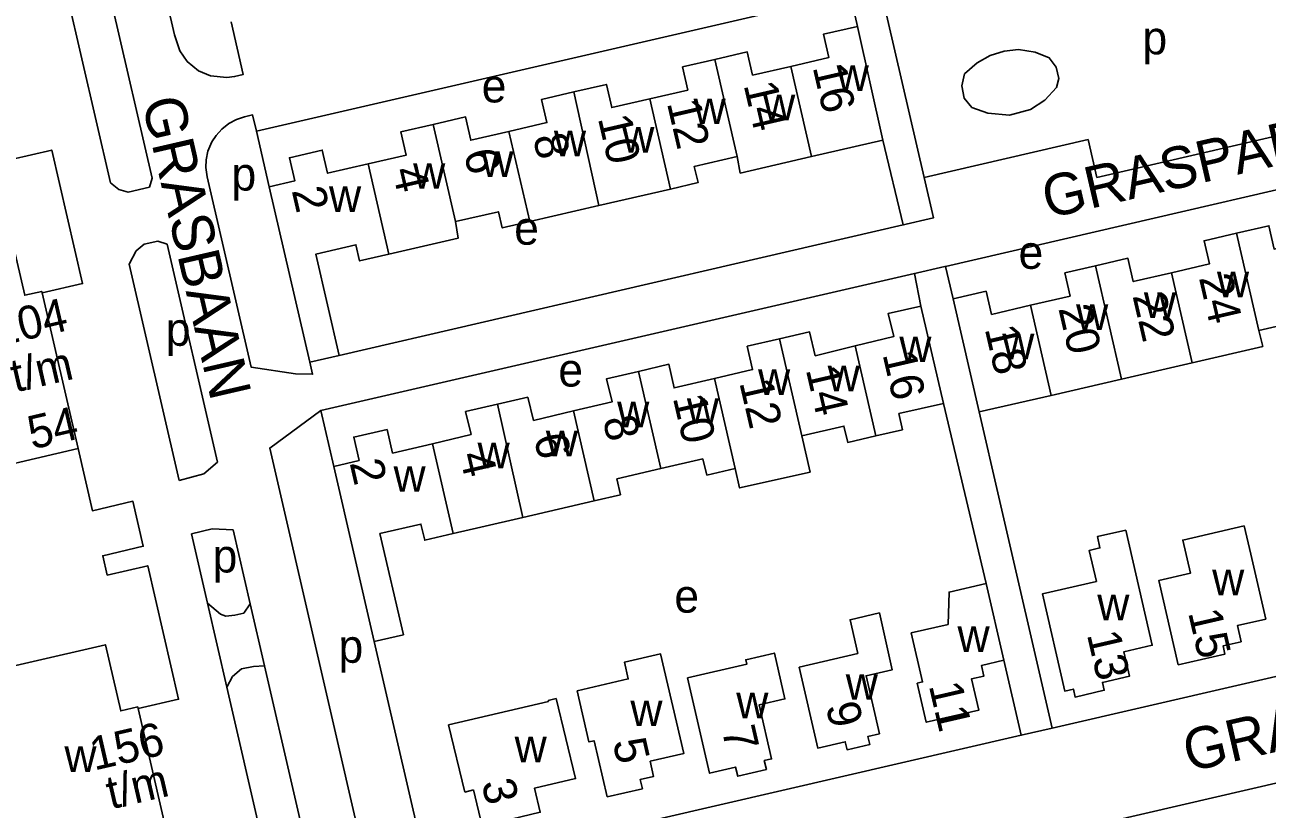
# Model space of a CAD drawing. Extents: x 155696 to 157795, y 382328 to 384028.
# Drawn here: x 156556.1 to 156705.6, y 383251.7 to 383346.1 of the extents above; entities that cross this region are included whole.
import ezdxf

# ---------------------------------------------------------------- set-up
doc = ezdxf.new("R2010")
doc.units = 0
for name, color, linetype in [('BLT_Basislijn', 7, 'Continuous'), ('BLT_Bebouwing', 7, 'Continuous'), ('BLT_Centroide', 7, 'Continuous'), ('BLT_Huisnummer', 7, 'Continuous'), ('BLT_Huisnummer_ tussenligend', 7, 'Continuous'), ('BLT_Huisnummer_reeks', 7, 'Continuous'), ('BLT_Onderverdeling_panden', 7, 'Continuous'), ('BLT_Straatnaam', 7, 'Continuous')]:
    doc.layers.add(name, color=color, linetype=linetype)

msp = doc.modelspace()

# ---------------------------------------------------------------- linework, layer by layer
at = {"layer": 'BLT_Basislijn'}
for p, q in [((156557.27, 383366.69), (156566.43, 383327.05)), ((156685.11, 383327.7), (156713.51, 383334.26)), ((156664.33, 383327.71), (156684.06, 383332.27)), ((156684.06, 383332.27), (156685.11, 383327.7)), ((156571.1, 383326.52), (156571.42, 383327.63)), ((156567.44, 383326.26), (156566.43, 383327.05)), ((156568.57, 383325.93), (156567.44, 383326.26)), ((156571.1, 383326.52), (156568.57, 383325.93)), ((156572.12, 383320.04), (156570.47, 383319.7)), ((156572.12, 383320.04), (156573.25, 383319.69)), ((156569.5, 383318.87), (156568.68, 383317.28)), ((156570.47, 383319.7), (156569.5, 383318.87)), ((156568.68, 383317.28), (156574.7, 383291.25)), ((156662.99, 383316.11), (156666.8, 383316.99)), ((156666.66, 383300.54), (156671.78, 383278.89)), ((156577.66, 383292.05), (156579.31, 383293.47)), ((156574.7, 383291.25), (156577.66, 383292.05)), ((156578.66, 383285.46), (156576.18, 383284.84)), ((156581.2, 383285.31), (156578.66, 383285.46)), ((156576.18, 383284.84), (156578.11, 383276.49)), ((156579.66, 383275.17), (156578.11, 383276.49)), ((156578.11, 383276.49), (156580.44, 383266.39)), ((156580.32, 383274.95), (156579.66, 383275.17)), ((156581.4, 383275.06), (156580.32, 383274.95)), ((156582.47, 383275.32), (156581.4, 383275.06)), ((156583.24, 383276.44), (156582.47, 383275.32)), ((156583.24, 383276.44), (156584.97, 383268.99)), ((156604.57, 383244.12), (156598.16, 383271.89)), ((156581.1, 383267.69), (156580.44, 383266.39)), ((156581.1, 383267.69), (156582.17, 383268.61)), ((156582.17, 383268.61), (156583.62, 383268.91)), ((156583.62, 383268.91), (156584.97, 383268.99)), ((156580.44, 383266.39), (156589.83, 383225.75)), ((156676, 383260.62), (156679.71, 383261.48))]:
    msp.add_line(p, q, dxfattribs=at)
for points in [[(156568.11, 383401.96), (156567.7, 383403.73), (156566.58, 383403.44), (156565.78, 383403.18), (156564.8, 383402.62), (156564.04, 383402.03), (156563.35, 383401.29), (156562.76, 383400.41), (156562.32, 383399.28), (156562.13, 383398.33), (156562.08, 383397.3), (156562.23, 383396.28), (156574.11, 383344.85), (156574.75, 383342.95), (156575.65, 383341.67), (156577.02, 383340.52), (156578.44, 383339.91), (156580.43, 383339.72), (156581.35, 383339.83), (156582.4, 383340.09), (156580.93, 383346.42)], [(156561.9, 383368.87), (156571.42, 383327.63)], [(156664.33, 383327.71), (156659.04, 383350.61), (156727.27, 383366.37), (156732.56, 383343.47)], [(156583.98, 383333.27), (156655.41, 383349.77), (156656.31, 383345.88)], [(156550.98, 383345.07), (156554.49, 383329.87), (156559.36, 383330.99), (156563.07, 383314.95), (156558.19, 383313.82)], [(156583.98, 383333.27), (156583.53, 383335.22), (156582.55, 383335), (156581.6, 383334.69), (156580.68, 383334.19), (156579.82, 383333.52), (156579.13, 383332.76), (156578.63, 383331.99), (156578.13, 383330.87), (156577.94, 383329.82), (156577.91, 383328.92), (156578.05, 383327.8), (156583.34, 383304.9), (156588.67, 383304.09), (156590.73, 383304.04), (156590.39, 383305.5)], [(156585.52, 383326.57), (156583.98, 383333.27)], [(156659.34, 383332.2), (156661.82, 383322), (156593.93, 383306.3)], [(156667.81, 383313.12), (156666.88, 383317.01), (156735.12, 383332.78)], [(156661.64, 383321.96), (156665.45, 383322.84), (156664.33, 383327.71)], [(156573.25, 383319.69), (156579.31, 383293.47)], [(156591.74, 383299.66), (156663.17, 383316.16), (156663.94, 383312.24)], [(156604.57, 383244.12), (156605.99, 383237.97), (156604.02, 383237.63), (156603.19, 383237.62), (156602.02, 383237.79), (156600.33, 383238.58), (156598.99, 383239.81), (156598.2, 383241.11), (156597.79, 383242.33), (156585.59, 383295.16), (156591.74, 383299.66)], [(156593.28, 383292.96), (156591.74, 383299.66)], [(156673.3, 383289.24), (156670.95, 383299.5)], [(156562.52, 383295.09), (156564.24, 383287.63), (156569.12, 383288.76), (156570.36, 383283.35), (156565.49, 383282.22), (156566.03, 383279.88), (156570.9, 383281.01), (156574.61, 383264.96), (156569.74, 383263.84)], [(156746.08, 383285.32), (156747.95, 383277.24), (156679.71, 383261.48), (156673.3, 383289.24)], [(156581.2, 383285.31), (156583.24, 383276.44)], [(156610.93, 383245.59), (156676, 383260.62), (156673.92, 383269.64)], [(156584.97, 383268.99), (156595.2, 383224.7)], [(156682.73, 383249.34), (156752.73, 383265.51), (156755.05, 383255.43)]]:
    msp.add_lwpolyline(points, dxfattribs=at)
msp.add_lwpolyline([(156670.7, 383341.51), (156672.25, 383342.36), (156673.94, 383342.9), (156675.69, 383343.1), (156677.7, 383342.79), (156679.37, 383342.09), (156680.19, 383340.97), (156680.53, 383339.62), (156680.27, 383338.52), (156678.84, 383337), (156677.11, 383335.86), (156674.58, 383335.18), (156671.97, 383335.43), (156670.08, 383336.1), (156669.13, 383337.24), (156668.85, 383338.71), (156669.17, 383340.16)], close=True, dxfattribs=at)
at = {"layer": 'BLT_Bebouwing'}
for p, q in [((156659.34, 383332.2), (156656.31, 383345.88)), ((156590.39, 383305.5), (156585.52, 383326.57)), ((156681.24, 383316.23), (156684.95, 383317.08)), ((156681.88, 383313.43), (156681.24, 383316.23)), ((156667.81, 383313.12), (156671.77, 383314.03)), ((156671.77, 383314.03), (156672.42, 383311.24)), ((156562.52, 383295.09), (156558.19, 383313.82)), ((156670.95, 383299.5), (156667.81, 383313.12)), ((156677.12, 383312.33), (156681.88, 383313.43)), ((156666.66, 383300.54), (156663.94, 383312.24)), ((156672.42, 383311.24), (156677.12, 383312.33)), ((156590.39, 383305.5), (156593.93, 383306.3)), ((156696.57, 383305.43), (156688.09, 383303.46)), ((156688.09, 383303.46), (156679.62, 383301.5)), ((156609.15, 383299.57), (156613, 383300.46)), ((156613, 383300.46), (156616.65, 383301.3)), ((156616.65, 383301.3), (156617.33, 383298.49)), ((156661.29, 383299.32), (156666.66, 383300.54)), ((156609.82, 383296.78), (156609.15, 383299.57)), ((156617.33, 383298.49), (156622.13, 383299.62)), ((156661.73, 383297.37), (156661.29, 383299.32)), ((156599.71, 383297.39), (156600.37, 383294.55)), ((156605.18, 383295.68), (156609.82, 383296.78)), ((156658.53, 383296.63), (156661.73, 383297.37)), ((156600.37, 383294.55), (156605.18, 383295.68)), ((156598.16, 383271.89), (156593.28, 383292.96)), ((156632.65, 383292.71), (156637.7, 383293.88)), ((156637.7, 383293.88), (156638.16, 383291.91)), ((156627.35, 383291.48), (156632.65, 383292.71)), ((156627.8, 383289.53), (156627.35, 383291.48)), ((156638.16, 383291.91), (156641.58, 383292.72)), ((156616.02, 383286.8), (156624.63, 383288.8)), ((156624.63, 383288.8), (156627.8, 383289.53)), ((156607.67, 383284.87), (156610.98, 383285.63)), ((156610.98, 383285.63), (156616.02, 383286.8)), ((156673.92, 383269.64), (156671.78, 383278.89)), ((156574.07, 383245.1), (156569.74, 383263.84)), ((156609.04, 383253.77), (156607.11, 383261.86))]:
    msp.add_line(p, q, dxfattribs=at)
for points in [[(156648.27, 383341.07), (156652.85, 383342.13), (156652.2, 383344.93), (156656.31, 383345.88)], [(156639.14, 383341.91), (156643.04, 383342.81), (156643.69, 383340.02), (156648.27, 383341.07)], [(156631.31, 383337.16), (156635.89, 383338.21), (156635.25, 383341.01), (156639.14, 383341.91)], [(156614.36, 383333.24), (156618.94, 383334.3), (156618.29, 383337.09), (156622.19, 383337.99)], [(156622.19, 383337.99), (156626.09, 383338.9), (156626.73, 383336.1), (156631.31, 383337.16)], [(156605.24, 383334.08), (156609.14, 383334.98), (156609.78, 383332.18), (156614.36, 383333.24)], [(156597.41, 383329.33), (156601.99, 383330.38), (156601.34, 383333.18), (156605.24, 383334.08)], [(156659.34, 383332.2), (156650.77, 383330.23)], [(156585.52, 383326.57), (156588.6, 383327.29), (156587.95, 383330.07), (156591.91, 383330.99), (156592.55, 383328.21), (156597.41, 383329.33)], [(156641.84, 383330.22), (156636.67, 383329.03), (156637.12, 383327.08), (156633.82, 383326.31)], [(156650.77, 383330.23), (156642.19, 383328.23), (156641.84, 383330.22)], [(156633.82, 383326.31), (156625.2, 383324.33)], [(156625.2, 383324.33), (156616.87, 383322.4)], [(156616.87, 383322.4), (156613.56, 383321.64), (156613.11, 383323.58), (156607.94, 383322.39)], [(156558.19, 383313.82), (156558.15, 383314.01), (156556.1, 383313.54), (156554.27, 383321.49), (156536.29, 383317.34), (156537.54, 383311.94), (156536.15, 383311.62)], [(156607.94, 383322.39), (156608.27, 383320.41), (156599.91, 383318.48)], [(156701.9, 383321), (156705.8, 383321.9), (156706.44, 383319.1), (156711.02, 383320.16)], [(156694.07, 383316.24), (156698.65, 383317.3), (156698, 383320.1), (156701.9, 383321)], [(156599.91, 383318.48), (156596.4, 383317.67), (156595.95, 383319.62), (156591.12, 383318.48), (156593.93, 383306.3)], [(156684.95, 383317.08), (156688.85, 383317.98), (156689.49, 383315.19), (156694.07, 383316.24)], [(156656.03, 383307.44), (156660.66, 383308.56), (156660, 383311.35), (156663.94, 383312.24)], [(156713.52, 383309.33), (156710.24, 383308.56), (156709.79, 383310.52), (156704.61, 383309.32)], [(156639.08, 383303.53), (156643.69, 383304.61), (156643.05, 383307.41), (156646.91, 383308.3)], [(156646.91, 383308.3), (156650.54, 383309.14), (156651.23, 383306.27), (156656.03, 383307.44)], [(156704.61, 383309.32), (156705.06, 383307.38), (156696.57, 383305.43)], [(156629.95, 383304.39), (156633.62, 383305.24), (156634.24, 383302.39), (156639.08, 383303.53)], [(156622.13, 383299.62), (156626.78, 383300.71), (156626.12, 383303.5), (156629.95, 383304.39)], [(156540.24, 383300.93), (156543.6, 383301.71), (156544.8, 383296.49), (156546.55, 383296.89), (156547.76, 383291.68), (156562.52, 383295.09)], [(156679.62, 383301.5), (156670.95, 383299.5)], [(156649.6, 383296.63), (156654.67, 383297.8), (156655.13, 383295.84), (156658.53, 383296.63)], [(156593.28, 383292.96), (156596.33, 383293.68), (156595.7, 383296.48), (156599.71, 383297.39)], [(156650.61, 383292.28), (156649.6, 383296.63)], [(156641.58, 383292.72), (156642.11, 383290.36), (156650.61, 383292.28)], [(156601.67, 383272.7), (156598.85, 383284.87), (156603.78, 383286.02), (156604.23, 383284.07), (156607.67, 383284.87)], [(156671.78, 383278.89), (156667.33, 383277.84), (156667.2, 383273.95), (156662.77, 383272.93), (156664.13, 383267.03), (156663.49, 383266.88), (156664.58, 383262.18), (156670.89, 383263.64), (156670.02, 383267.39), (156671.52, 383267.73), (156671.23, 383269.02), (156673.92, 383269.64)], [(156598.16, 383271.89), (156601.67, 383272.7)], [(156547.69, 383261.63), (156549.08, 383261.95), (156547.84, 383267.36), (156565.81, 383271.51), (156567.65, 383263.55), (156569.7, 383264.03), (156569.74, 383263.84)], [(156607.11, 383261.86), (156619.11, 383264.7), (156619.09, 383264.81), (156620.04, 383265.04), (156622.38, 383255.42), (156617.46, 383254.28), (156618.13, 383251.36), (156611.13, 383249.7), (156610.12, 383254.05)], [(156610.12, 383254.05), (156609.04, 383253.77)]]:
    msp.add_lwpolyline(points, dxfattribs=at)
for points in [[(156694.89, 383269.09), (156700.52, 383270.39), (156700.29, 383271.36), (156702.46, 383271.86), (156702.01, 383273.81), (156705.42, 383274.6), (156703.62, 383282.39), (156702.83, 383285.8), (156695.44, 383284.1), (156696.37, 383280.1), (156692.55, 383279.22)], [(156688.58, 383285.3), (156685.17, 383284.51), (156685.48, 383283.15), (156684.19, 383282.85), (156685.05, 383279.13), (156678.55, 383277.63), (156681.25, 383265.94), (156682.28, 383266.17), (156682.49, 383265.22), (156685.99, 383266.03), (156685.77, 383266.98), (156689.04, 383267.74), (156688.37, 383270.66), (156691.78, 383271.45)], [(156649.28, 383268.83), (156656.34, 383270.46), (156655.41, 383274.51), (156658.94, 383275.33), (156660.49, 383268.51), (156657.33, 383267.78), (156658.94, 383260.8), (156657.56, 383260.48), (156657.79, 383259.52), (156655.06, 383258.88), (156654.84, 383259.84), (156651.52, 383259.08)], [(156635.86, 383267.52), (156642.98, 383269.16), (156642.86, 383269.7), (156646.31, 383270.5), (156647.58, 383265), (156644.46, 383264.28), (156645.96, 383257.78), (156645.09, 383257.58), (156645.34, 383256.49), (156641.89, 383255.7), (156641.64, 383256.79), (156638.5, 383256.06)], [(156622.58, 383265.97), (156628.72, 383267.39), (156628.26, 383269.4), (156632.62, 383270.41), (156635.39, 383258.42), (156631.36, 383257.49), (156631.78, 383255.68), (156630.16, 383255.31), (156630.42, 383254.2), (156626.19, 383253.22), (156624.61, 383259.96), (156623.99, 383259.82)]]:
    msp.add_lwpolyline(points, close=True, dxfattribs=at)
at = {"layer": 'BLT_Onderverdeling_panden'}
for p, q in [((156641.84, 383330.22), (156639.14, 383341.91)), ((156650.77, 383330.23), (156648.27, 383341.07)), ((156625.2, 383324.33), (156622.19, 383337.99)), ((156633.82, 383326.31), (156631.31, 383337.16)), ((156607.94, 383322.39), (156605.24, 383334.08)), ((156616.87, 383322.4), (156614.36, 383333.24)), ((156599.91, 383318.48), (156597.41, 383329.33)), ((156704.61, 383309.32), (156701.9, 383321)), ((156688.09, 383303.46), (156684.95, 383317.08)), ((156696.57, 383305.43), (156694.07, 383316.24)), ((156679.62, 383301.5), (156677.12, 383312.33)), ((156649.6, 383296.63), (156646.91, 383308.3)), ((156658.53, 383296.63), (156656.03, 383307.44)), ((156632.65, 383292.71), (156629.95, 383304.39)), ((156641.58, 383292.72), (156639.08, 383303.53)), ((156616.02, 383286.8), (156613, 383300.46)), ((156624.63, 383288.8), (156622.13, 383299.62)), ((156607.67, 383284.87), (156605.18, 383295.68))]:
    msp.add_line(p, q, dxfattribs=at)

# ---------------------------------------------------------------- texts
at = {"layer": 'BLT_Centroide'}
for s, p in [('p', (156690.59, 383342.51)), ('w', (156653.8, 383338.11)), ('e', (156611.09, 383336.73)), ('w', (156636.58, 383334.12)), ('w', (156644.95, 383334.59)), ('w', (156619.78, 383330.25)), ('w', (156628, 383330.69)), ('w', (156611.05, 383327.78)), ('p', (156580.98, 383326.13)), ('w', (156602.84, 383326.34)), ('w', (156592.72, 383323.55)), ('e', (156615, 383319.62)), ('e', (156675.68, 383316.72)), ('w', (156699.56, 383313.3)), ('w', (156690.77, 383310.8)), ('w', (156682.61, 383309.36)), ('p', (156573.08, 383307.46)), ('w', (156661.34, 383305.5)), ('w', (156673.72, 383305.83)), ('e', (156620.31, 383302.56)), ('w', (156652.72, 383301.98)), ('w', (156644.34, 383301.56)), ('w', (156627.39, 383297.66)), ('w', (156635.77, 383298.09)), ('w', (156618.81, 383294.17)), ('w', (156610.59, 383292.72)), ('w', (156600.48, 383289.91)), ('p', (156578.71, 383280.2)), ('w', (156698.98, 383277.47)), ('e', (156634.27, 383275.37)), ('w', (156685.16, 383274.45)), ('w', (156668.34, 383270.64)), ('p', (156593.86, 383269.34)), ('w', (156654.89, 383264.89)), ('w', (156628.98, 383261.72)), ('w', (156641.72, 383262.66)), ('w', (156615.05, 383257.38)), ('w', (156560.88, 383256.22))]:
    msp.add_text(s, height=4, dxfattribs=at).set_placement(p)
at = {"layer": 'BLT_Huisnummer'}
for s, rotation, p in [('16', 283.0091, (156650.89, 383340.99)), ('12', 283.0091, (156633.36, 383336.67)), ('6', 283.0091, (156608.92, 383330.72)), ('2', 283.0091, (156588.21, 383326.15)), ('22', 283.0054, (156689.38, 383313.49)), ('18', 283.0054, (156671.6, 383309.52)), ('16', 283.0054, (156659.3, 383306.45)), ('12', 283.0054, (156642.07, 383303.05)), ('10', 283.0054, (156634.07, 383301.22)), ('6', 283.0054, (156617.33, 383296.48)), ('2', 283.0054, (156595.18, 383293.39)), ('15', 283.0062, (156696.07, 383275.39)), ('13', 283.0062, (156683.89, 383272.76)), ('11', 283.0083, (156664.87, 383266.61)), ('9', 283.0062, (156652.47, 383264.17)), ('7', 283.0062, (156639.95, 383261.3)), ('5', 282.6612, (156626.83, 383259.85)), ('3', 283.3449, (156611.04, 383254.92))]:
    msp.add_text(s, height=4, rotation=rotation, dxfattribs=at).set_placement(p)
at = {"layer": 'BLT_Huisnummer_ tussenligend'}
for s, rotation, p in [('14', 283.0091, (156642.59, 383338.84)), ('10', 283.0091, (156625.05, 383334.84)), ('8', 283.0091, (156617.23, 383332.55)), ('4', 283.0091, (156600.31, 383328.56)), ('24', 283.0054, (156697.37, 383315.66)), ('20', 283.0054, (156680.46, 383311.97)), ('14', 283.0054, (156650.07, 383304.61)), ('8', 283.0054, (156625.63, 383298.63)), ('4', 283.0054, (156608.4, 383294.33))]:
    msp.add_text(s, height=4, rotation=rotation, dxfattribs=at).set_placement(p)
at = {"layer": 'BLT_Huisnummer_reeks'}
for s, p in [('104', (156552.83, 383307.36)), ('t/m', (156554.95, 383301.84)), ('54', (156556.99, 383294.98)), ('156', (156564.47, 383256.37)), ('t/m', (156566.45, 383251.7))]:
    msp.add_text(s, height=4, rotation=13.0058, dxfattribs=at).set_placement(p)
at = {"layer": 'BLT_Straatnaam'}
for s, rotation, p in [('GRASPARKIET', 13.0063, (156679.2, 383322.75)), ('GRASBAAN', 283.0066, (156570.19, 383336.86)), ('GRASSIJSJE', 13.0062, (156696.16, 383256.19))]:
    msp.add_text(s, height=5, rotation=rotation, dxfattribs=at).set_placement(p)

doc.saveas('drawing.dxf')
